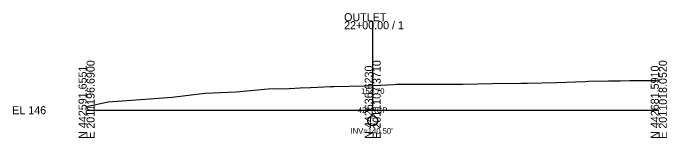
# Model space of a CAD drawing. Extents: x -26 to 1203, y -15 to 9526.
# Drawn here: x 974.3 to 1202.8, y 1990.3 to 2034 of the extents above; entities that cross this region are included whole.
import ezdxf

# ---------------------------------------------------------------- set-up
doc = ezdxf.new("R2010")
doc.units = 0
for name, color, linetype in [('Exist Cross Section Cell', 7, 'Continuous'), ('Exist XS Center Line Elevation Label', 7, 'Continuous'), ('Exist XS Ground Line', 7, 'Continuous'), ('Prop XSC Text', 7, 'Continuous')]:
    doc.layers.add(name, color=color, linetype=linetype)

msp = doc.modelspace()

# ---------------------------------------------------------------- linework, layer by layer
at = {"layer": 'Exist Cross Section Cell'}
for p, q in [((1100, 2000), (1100, 2031.13)), ((1000, 2000), (1100, 2000)), ((1100, 2000), (1200, 2000))]:
    msp.add_line(p, q, dxfattribs=at)
at = {"layer": 'Exist XS Ground Line'}
msp.add_lwpolyline([(1000, 2001.32), (1007.49, 2002.93), (1018.82, 2003.78), (1029.88, 2004.61), (1041.36, 2005.99), (1052.27, 2006.48), (1063.47, 2007.42), (1070.77, 2007.6), (1074.66, 2007.79), (1078.22, 2007.93), (1085.27, 2008.26), (1085.86, 2008.27), (1086.46, 2008.3), (1097.06, 2008.57), (1100, 2008.7), (1107.51, 2009.04), (1108.25, 2009.06), (1109.01, 2009.06), (1119.45, 2009.06), (1129.75, 2009.07), (1130.64, 2009.08), (1131.55, 2009.1), (1141.84, 2009.31), (1151.99, 2009.45), (1152.68, 2009.46), (1153.04, 2009.46), (1154.1, 2009.48), (1164.23, 2009.67), (1174.22, 2010.07), (1175.43, 2010.12), (1182.47, 2010.3), (1186.62, 2010.33), (1189.92, 2010.36), (1196.46, 2010.38), (1197.82, 2010.36), (1199.2, 2010.34), (1200, 2010.32)], dxfattribs=at)
at = {"layer": 'Prop XSC Text'}
msp.add_circle((1100, 1996.25), 1.75, dxfattribs=at)

# ---------------------------------------------------------------- texts
at = {"layer": 'Exist Cross Section Cell'}
for s, p in [('OUTLET', (1090, 2031.13)), ('22+00.00 / 1', (1090, 2028.33)), ('EL 146', (974, 1998.6))]:
    msp.add_text(s, height=2.8, dxfattribs=at).set_placement(p)
for s, p in [('E 2011196.6900', (1002.8, 1990)), ('E 2011107.3710', (1102.8, 1990)), ('E 2011018.0520', (1202.8, 1990)), ('N 442591.6551', (1000, 1990)), ('N 442636.6230', (1100, 1990)), ('N 442681.5910', (1200, 1990))]:
    msp.add_text(s, height=2.8, rotation=90, dxfattribs=at).set_placement(p)
at = {"layer": 'Exist XS Center Line Elevation Label'}
msp.add_text('154.70', height=2, dxfattribs=at).set_placement((1095.95, 2005.7))
at = {"layer": 'Prop XSC Text'}
for s, p in [('42" RCP', (1094.81, 1999)), ("INV=140.50'", (1092.26, 1991.76))]:
    msp.add_text(s, height=2, dxfattribs=at).set_placement(p)

doc.saveas('drawing.dxf')
